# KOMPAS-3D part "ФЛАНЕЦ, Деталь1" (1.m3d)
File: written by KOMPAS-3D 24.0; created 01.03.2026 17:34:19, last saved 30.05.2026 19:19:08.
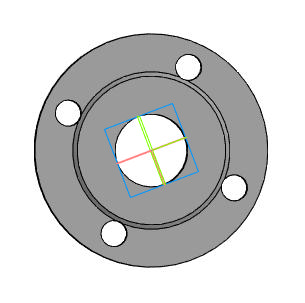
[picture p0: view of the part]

Document properties: Автор: R2D2; Полное имя файла: E:\Работа\Зайцев\GVWR3131M-2W-F-S Задвижка клиновая с выдвижным штоком DN.ru Ду50-100 Ру40\исходные материалы\DN50\1.m3d

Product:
- Part/product: ФЛАНЕЦ  | designation Деталь1
    Масса: 2.444901
    additional columns: Типовые
- Part/product: ФЛАНЕЦ  | designation Деталь1-01
    Масса: 3.87439
    additional columns: Типовые

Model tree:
1. Эскиз:2
2. Элемент вращения:1
     Угол 1 = 360
3. Эскиз:3  (with: Грань.Элемент вращения:1)
4. Элемент выдавливания:2
     Расстояние 1 = 3; Расстояние 2 = 17
5. Массив по концентрической сетке:1  (with: Элемент выдавливания:2, Эскиз:3, Грань.Элемент вращения:1)  (4 pattern instances)
     Шаг 2 = 360

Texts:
  Деталь1
  Деталь1-01
  Линейный размер с обрывом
